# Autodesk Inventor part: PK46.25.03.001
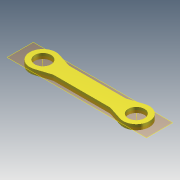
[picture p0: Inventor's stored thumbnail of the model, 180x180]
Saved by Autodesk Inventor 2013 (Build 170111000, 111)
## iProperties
Shininess: 64.0
Length Units: 11269
Angle Units: 11279
Time Units: 11290
Mass Units: 11283
Length Display Precision: 3
Angle Display Precision: 2
Compacted: True
Part Number: PK46.25.03.001
Document SubType Name: Modeling
Created: 2004-11
Material: Steel, Mild
Designer: Salex
Manufacturer: Standard
Standards Organization: Custom
Density: 7.86 g/cm^3
Density: 0.0
Volumn: 0.0
Area: 0.0
PropertySet Name: Model Information
Control State: 0
Master: False
Checked Out: False
Checked Out Date: 2008-10-15
Last Check In Date: 2008-10-15
Author: Salex
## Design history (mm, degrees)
sketch "Sketch1"
  geometry: L1 (3047.033, -1142.556)-(2332.033, -1142.556); L2 (2907.033, -1082.556)-(2472.033, -1082.556); L3 (2362.664, -1047.363)-(2472.033, -1082.556); L4 (2362.664, -1237.749)-(2472.033, -1202.556); L5 (2907.033, -1202.556)-(3016.401, -1237.749); L6 (2907.033, -1082.556)-(3016.401, -1047.363); L7 (2472.033, -1202.556)-(2907.033, -1202.556); C1 r 62.5 at (3047.033, -1142.556); C2 r 62.5 at (2332.033, -1142.556); A1 r 100 centre (3047.033, -1142.556) between (3016.401, -1237.749) and (3016.401, -1047.363); A2 r 100 centre (2332.033, -1142.556) between (2362.664, -1047.363) and (2362.664, -1237.749)
  constraints: 14 end point, 4 centre point, 4 point on circle, 4 tangent, 3 equal length, 3 parallel, 2 coincident, 2 equal radius, 1 other
  dimensions: "d0" = 0 vertical distance of L1.end L1.start; "d1" = 715 distance of L1.end L1.start; "d2" = 200 diameter of A1; "d3" = 60 distance between parallel lines of L1 L2; "d5" = 125 diameter of C1; "d9" = 140 horizontal distance of L2.end L1.end
extrude "Extrusion1" new body sketch "Sketch1" distance "d6" = 40; taper "d7" = 0 deg
fillet "Fillet1" dims "d8" = 50
workplane "Work Plane1"
workaxis "Work Axis1"
workaxis "Work Axis2"
body "Solid1"
